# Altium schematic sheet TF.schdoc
size 297 x 209 mm; Symbol: Drawing-Symbol_A4; Company: 嘉立创EDA; Version: V1.0; Page Size: A4; @Project Name: ExoAnchor-ESP32P4; @Update Date: 2026-07-09; @Create Date: 2026-07-09; Device: Drawing-Symbol_A4; @Board Name: ESP32P4_Prototype_V2.1; @Page Name: P5; @Create Time: 00:52:27; @Page Count: 9; @Page No: 0; @Schematic Name: SCH_6; @Update Time: 00:52:27; @Assembly Variant: Basic; Border: 1; Title Block Position: 3; Size: A4; Width: 1170; Height: 825; Region Start: 1; X Region Count: 6; Y Region Count: 4; Blade Width: 10
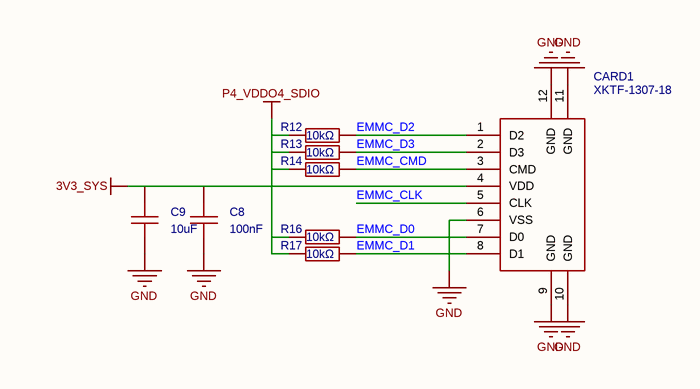
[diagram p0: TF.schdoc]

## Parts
C8  100nF  [C0603]
C9  10uF  [C0805]
CARD1  XKTF-1307-18  [TF-SMD_XKTF-1307-18]
R12  10kΩ  [R0402]
R13  10kΩ  [R0402]
R14  10kΩ  [R0402]
R16  10kΩ  [R0402]
R17  10kΩ  [R0402]

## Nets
3V3_SYS: C8.2 C9.2 CARD1.4(VDD)
GND: C8.1 C9.1 CARD1.6(VSS) CARD1.9(GND) CARD1.10(GND) CARD1.11(GND) CARD1.12(GND)
P4_VDDO4_SDIO: R12.1 R13.1 R14.1 R16.1 R17.1
EMMC_CLK: CARD1.5(CLK)
EMMC_CMD: CARD1.3(CMD) R14.2
EMMC_D0: CARD1.7(D0) R16.2
EMMC_D1: CARD1.8(D1) R17.2
EMMC_D2: CARD1.1(D2) R12.2
EMMC_D3: CARD1.2(D3) R13.2

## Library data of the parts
C8 = CC0603KRX7R9BB104: 容值:100nF;精度:±10%;额定电压:50V;温度系数:X7R;; Manufacturer: YAGEO(国巨); Add into BOM: yes; 3D Model: ac125912035d415993ca9572d50418b1; 3D Model Transform: 62.992,31.496,0,0,0,0,0,0,0; Tolerance: ±10%; Voltage Rating: 50V; Temperature Coefficient: X7R; ModelName: C0603_L1.6-W0.8-H0.8
C9 = CL21A106KAYNNNE_C15850: 容值:10uF;精度:±10%;额定电压:25V;温度系数:X5R;; Manufacturer: SAMSUNG(三星); Add into BOM: yes; 3D Model: 1ba041120af144c991958decab20d241; 3D Model Transform: 78.74,51.181,0,0,0,0,0,0.0005,0; Tolerance: ±10%; Voltage Rating: 25V; Temperature Coefficient: X5R; ModelName: C0805_L2.0-W1.3-H1.3
CARD1 = XKTF-1307-18: 卡连接方式:翻盖式;卡类型:MicroSD卡(TF卡);连接器类型:卡座;本体最大高度:1.8mm;工作温度:-25℃~+80℃;; Manufacturer: XKB Connection(中国星坤); AddInBom: yes; ModelId: 727fcc349d18420790626965bab3a19c0819f05c4eef4c71ace90d822a990e87; ModelTransform: 574.86113,527.54824,0,0,0,0,0,47.245,0; Card Connection Mode: 翻盖式; Connector Type: 卡座
R12-R14 R16 R17 = FRC0402F1002TS: 电阻类型:厚膜电阻;阻值:10kΩ;精度:±1%;功率:62.5mW;工作电压:50V;温度系数:±100ppm/℃;; Manufacturer: FOJAN(富捷); Symbol: 电阻; 3D Model: 98c88bc2b9094f218f3a3e30a70127380819f05c4eef4c71ace90d822a990e87; 3D Model Transform: 39.37,19.685,0,0,0,0,0,0,0; AddInBom: yes; ModelName: R0402_L1.0-W0.5-H0.4; Tolerance: ±1%; Power(Watts): 62.5mW; Voltage-Supply(Max): 50V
